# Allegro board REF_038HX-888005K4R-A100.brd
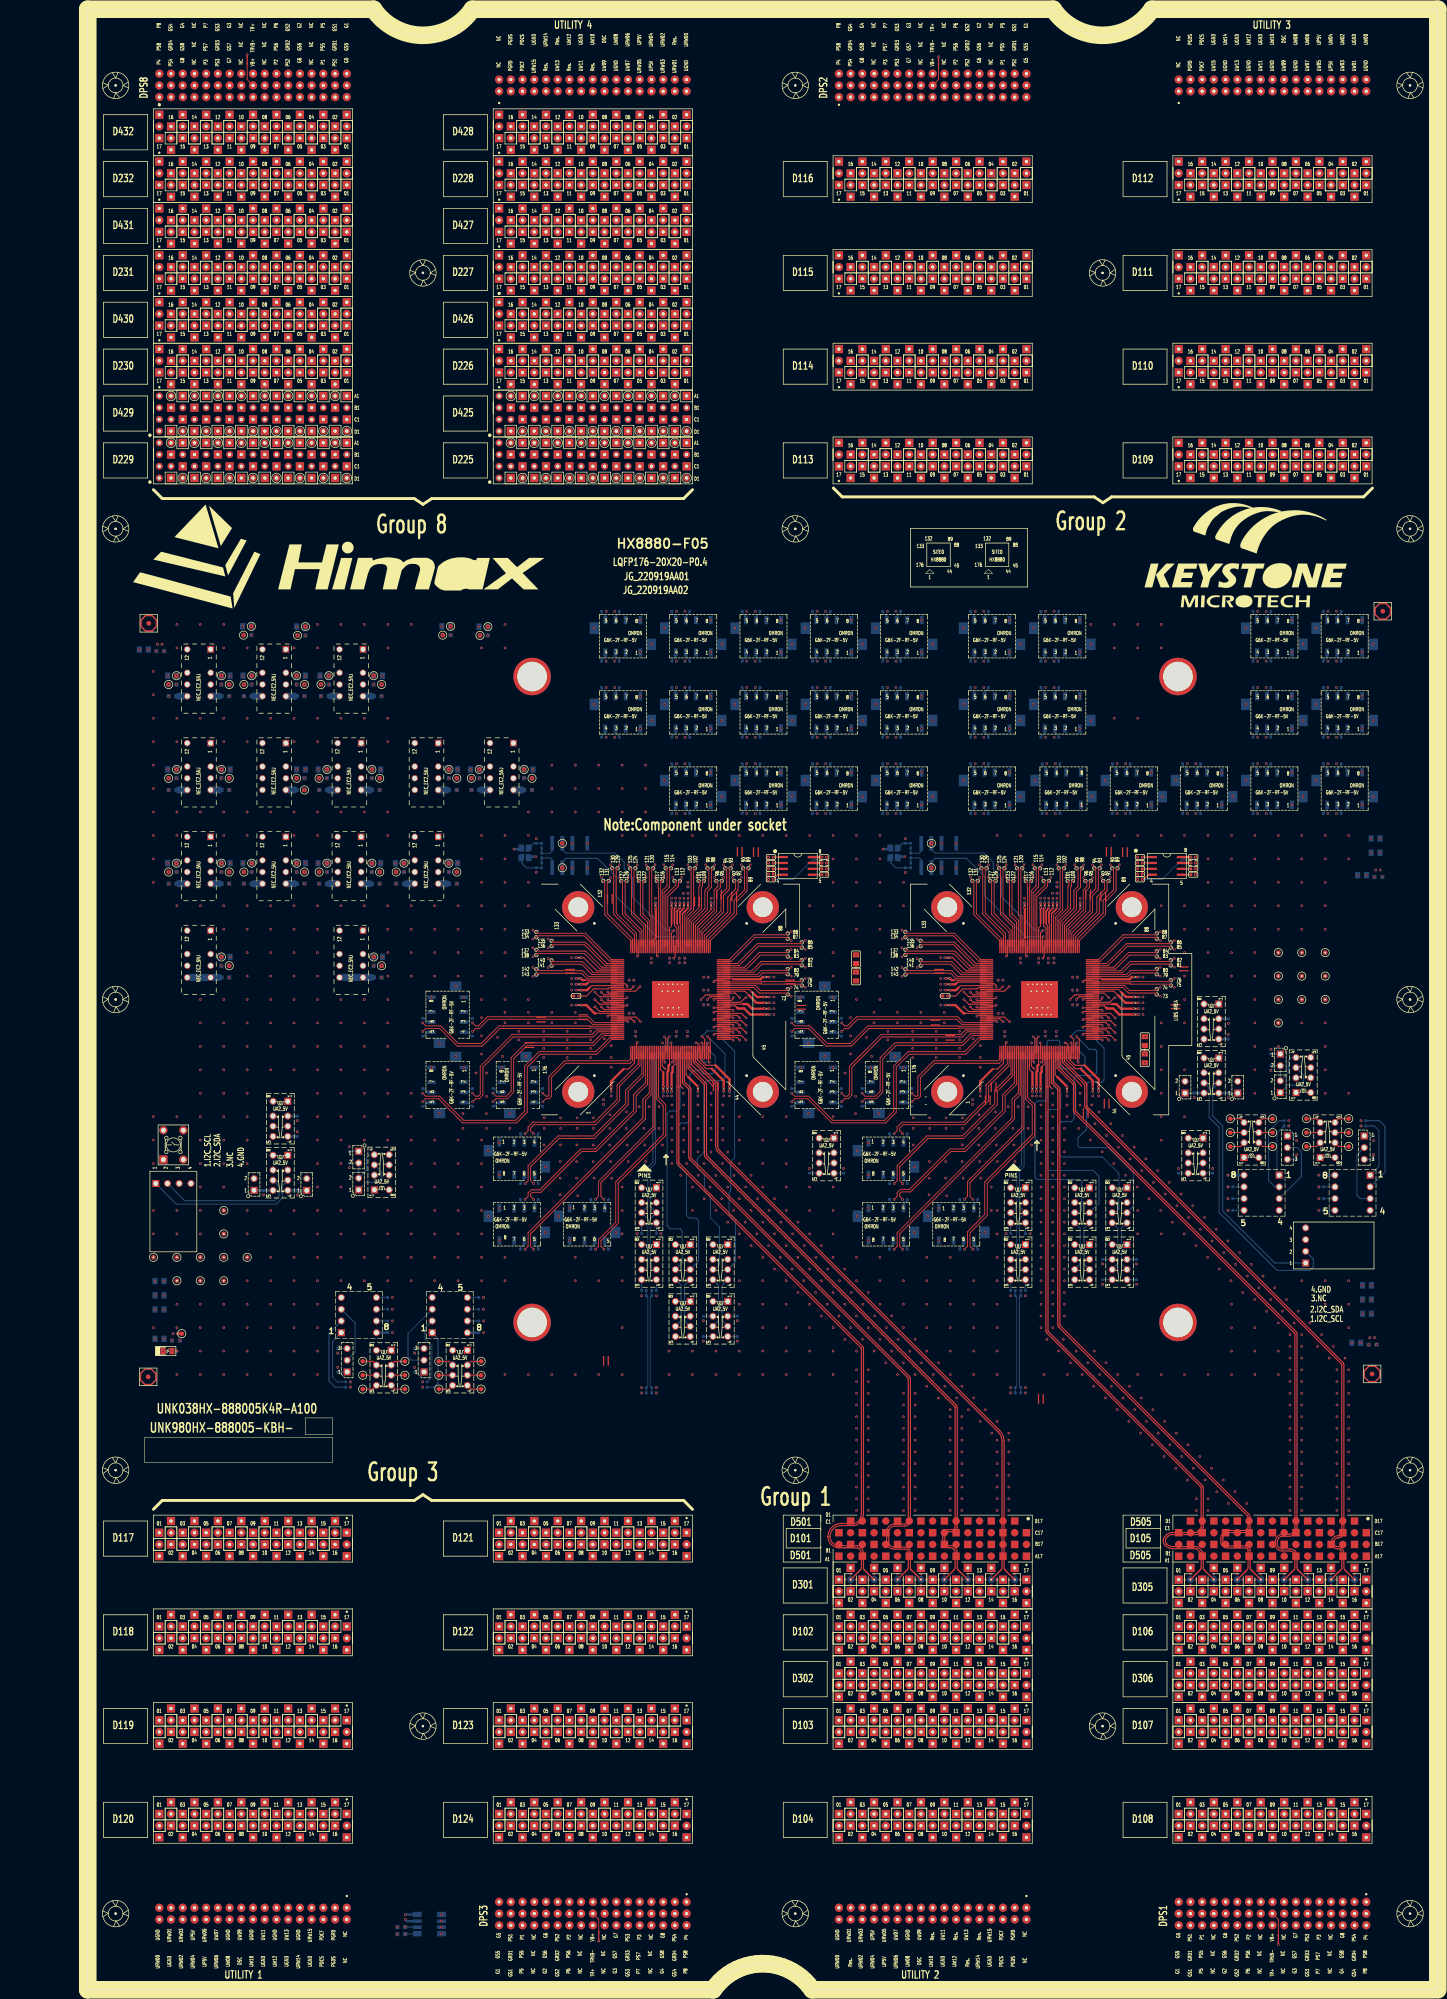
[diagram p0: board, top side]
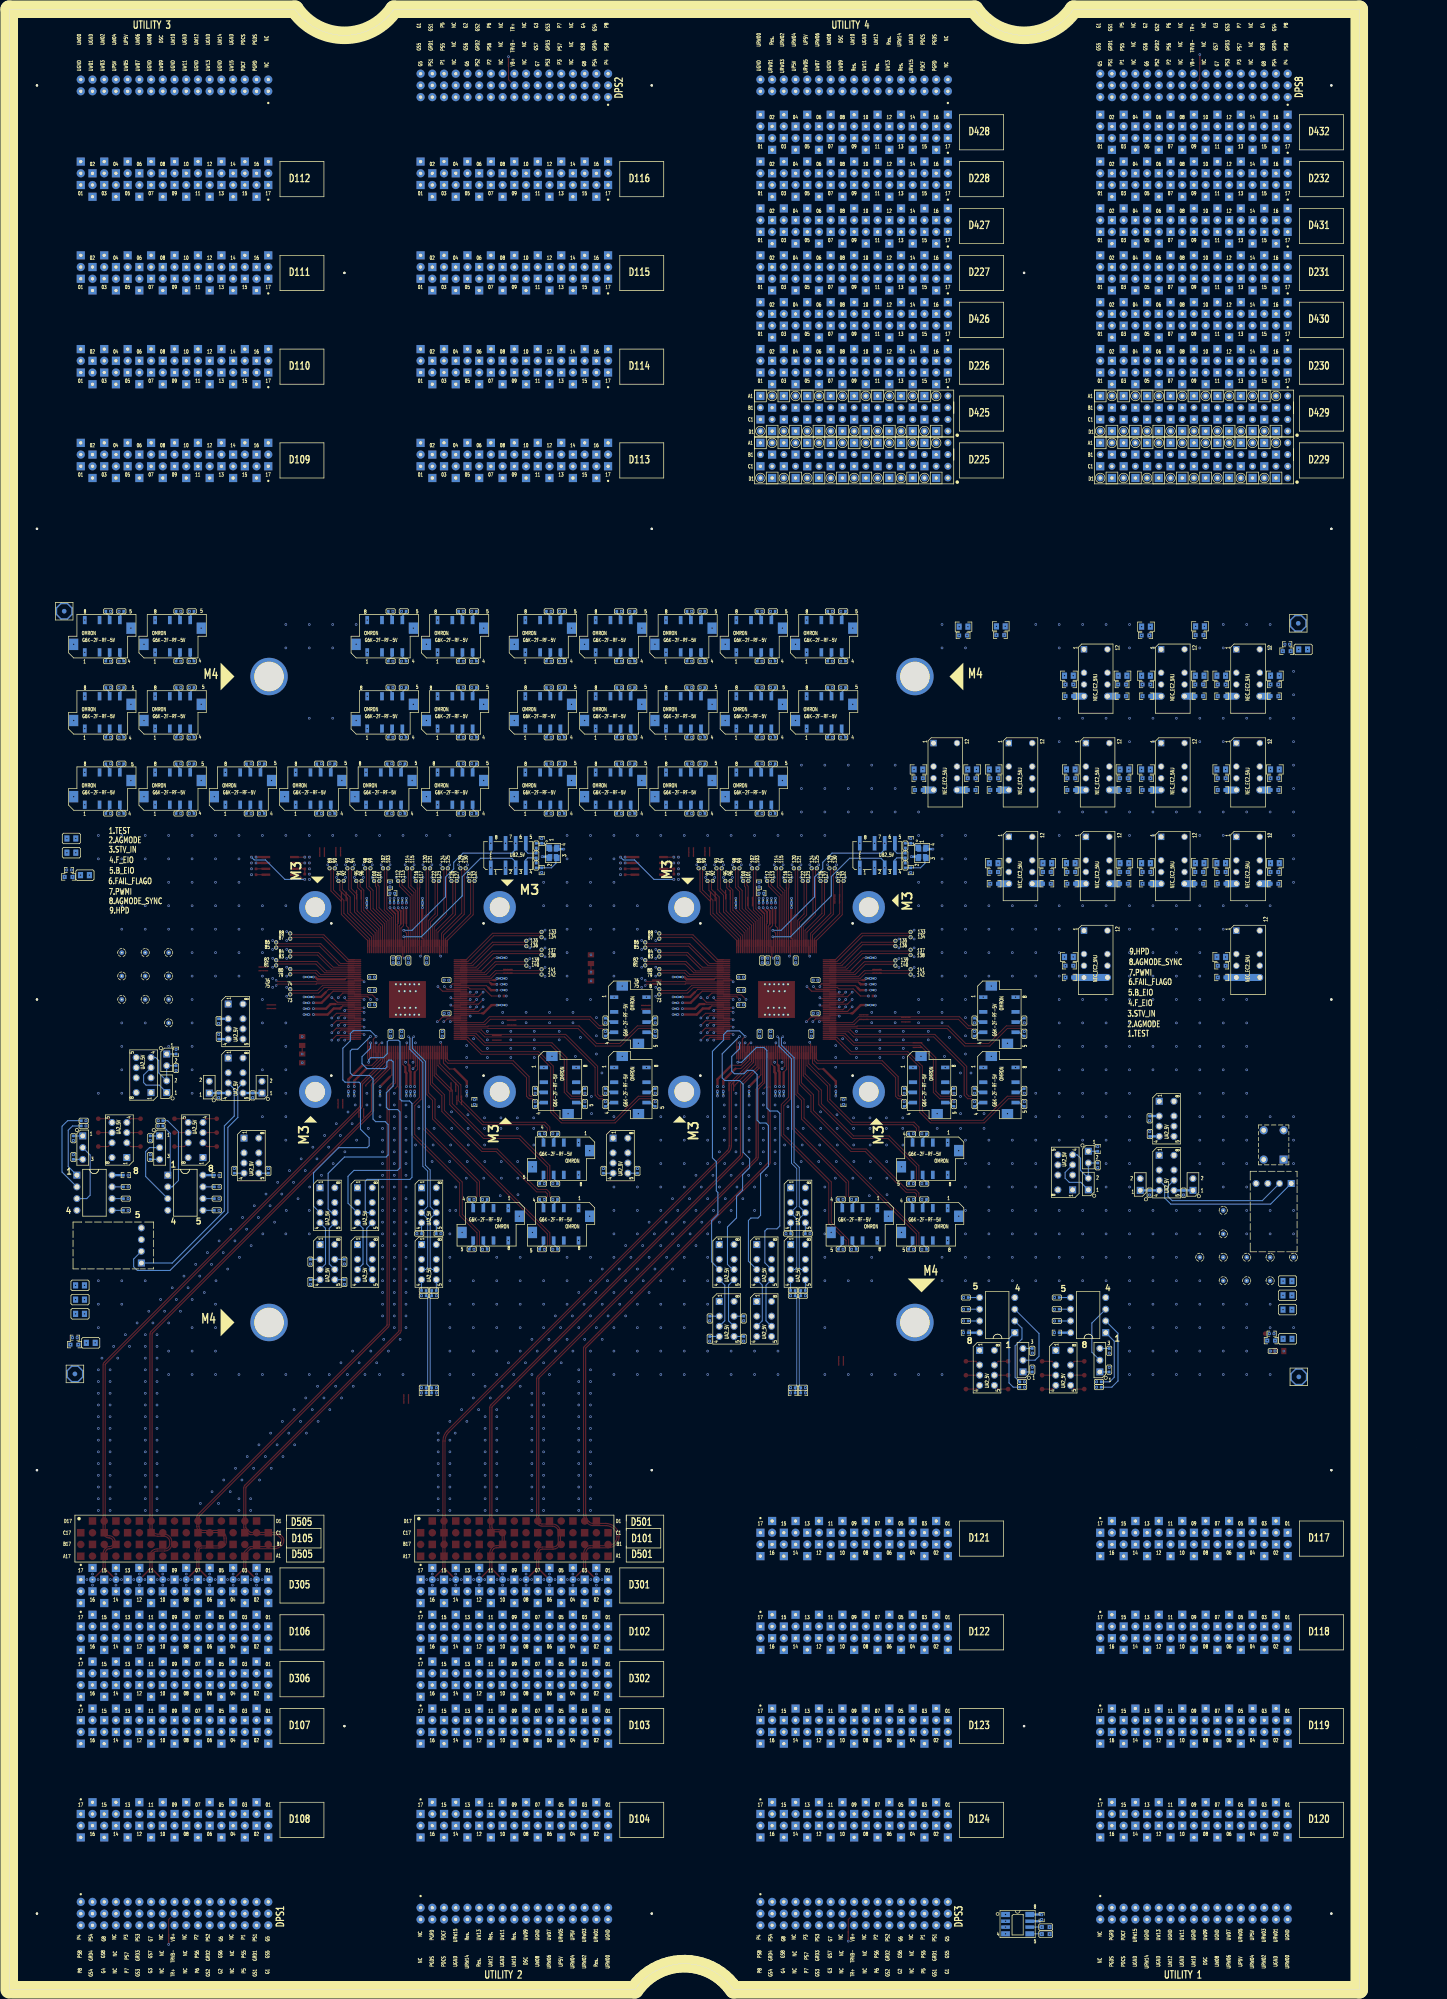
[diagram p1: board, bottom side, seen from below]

Outline 292.64 x 429.26 mm; copper layers: TOP, L02_GND, L03_SIGNAL, L04_GND, L05_SIGNAL, L06_GND, L07_SIGNAL, L08_GND, L09_POWER, L10_GND, L11_POWER, L12_USER, L13_CBIT, L14_POWER, L15_GND, L16_POWER, L17_GND, L18_POWER, L19_GND, L20_SIGNAL, L21_GND, L22_SIGNAL, L23_GND, BOTTOM. Coordinates in mm from the lower left corner of the outline.

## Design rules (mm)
net group 2AUX: nets S1_2AUX+ S1_2AUX-
net group D231_MCB1_E: nets D231_MCB1_E+ D231_MCB1_E-
net group D231_MCB1_EE: nets D231_MCB1_EE+ D231_MCB1_EE-
net group D231_MCB1_F: nets D231_MCB1_F+ D231_MCB1_F-
net group D231_MCB1_FF: nets D231_MCB1_FF+ D231_MCB1_FF-
net group D231_MCB1_G: nets D231_MCB1_G+ D231_MCB1_G-
net group D231_MCB1_GG: nets D231_MCB1_GG+ D231_MCB1_GG-
net group D231_MCB1_H: nets D231_MCB1_H+ D231_MCB1_H-
net group D231_MCB1_HH: nets D231_MCB1_HH+ D231_MCB1_HH-
net group D232_MCB1_E: nets D232_MCB1_E+ D232_MCB1_E-
net group D232_MCB1_EE: nets D232_MCB1_EE+ D232_MCB1_EE-
net group D232_MCB1_F: nets D232_MCB1_F+ D232_MCB1_F-
net group D232_MCB1_FF: nets D232_MCB1_FF+ D232_MCB1_FF-
net group D232_MCB1_G: nets D232_MCB1_G+ D232_MCB1_G-
net group D232_MCB1_GG: nets D232_MCB1_GG+ D232_MCB1_GG-
net group D232_MCB1_H: nets D232_MCB1_H+ D232_MCB1_H-
net group D232_MCB1_HH: nets D232_MCB1_HH+ D232_MCB1_HH-
net group D431_MCB1_A: nets D431_MCB1_A+ D431_MCB1_A-
net group D431_MCB1_AA: nets D431_MCB1_AA+ D431_MCB1_AA-
net group D431_MCB1_B: nets D431_MCB1_B+ D431_MCB1_B-
net group D431_MCB1_BB: nets D431_MCB1_BB+ D431_MCB1_BB-
net group D431_MCB1_C: nets D431_MCB1_C+ D431_MCB1_C-
net group D431_MCB1_CC: nets D431_MCB1_CC+ D431_MCB1_CC-
net group D431_MCB1_D: nets D431_MCB1_D+ D431_MCB1_D-
net group D431_MCB1_DD: nets D431_MCB1_DD+ D431_MCB1_DD-
net group D432_MCB1_A: nets D432_MCB1_A+ D432_MCB1_A-
net group D432_MCB1_AA: nets D432_MCB1_AA+ D432_MCB1_AA-
net group D432_MCB1_B: nets D432_MCB1_B+ D432_MCB1_B-
net group D432_MCB1_BB: nets D432_MCB1_BB+ D432_MCB1_BB-
net group D432_MCB1_C: nets D432_MCB1_C+ D432_MCB1_C-
net group D432_MCB1_CC: nets D432_MCB1_CC+ D432_MCB1_CC-
net group D432_MCB1_D: nets D432_MCB1_D+ D432_MCB1_D-
net group D432_MCB1_DD: nets D432_MCB1_DD+ D432_MCB1_DD-
net group S1_1AUX: nets S1_1AUX+ S1_1AUX-
net group S1_AUXCH: nets S1_AUXCH+ S1_AUXCH-
net group S2_1AUX: nets S2_1AUX+ S2_1AUX-
net group S2_2AUX: nets S2_2AUX+ S2_2AUX-
net group S2_AUXCH: nets S2_AUXCH+ S2_AUXCH-
net group AUX1: nets D12013 D12015 D12406 D12408
net group AUX2: nets D11801 D11803 D12201 D12203
net group CH: nets D10305 D10307 D10309 D10315 D10401 D10402 D10403 D10404 D10405 D10406 D10411 D10416 D10705 D10707 D10709 D10715 D10801 D10802 D10803 D10804 D10805 D10806 D10811 D10816 D11902 D11906 D11911 D12005 D12006 D12007 D12009 D12011 D12105 D12109 D12305 D12312 D12411 D12413 D12415 D12416
net group ELV_RX: nets D11805 D11806 D11807 D11808 D11809 D11810 D11811 D11812 D11813 D11814 D11815 D11816 D12205 D12206 D12207 D12208 D12209 D12210 D12211 D12212 D12213 D12214 D12215 D12216
net group FLASH: nets S1_SPI_CSN S1_SPI_SCK S1_SPI_SDI S1_SPI_SDO S2_SPI_CSN S2_SPI_SCK S2_SPI_SDI S2_SPI_SDO
net group ISP_TX: nets D10901 D10902 D10903 D10904 D10905 D10906 D10907 D10908 D10909 D10910 D10911 D10912 D10913 D10914 D10915 D10916 D11001 D11002 D11003 D11004 D11005 D11006 D11007 D11008 D11009 D11010 D11011 D11012 D11013 D11014 D11015 D11016 D11101 D11102 D11103 D11104 D11105 D11106 D11107 D11108 D11109 D11110 D11111 D11112 D11113 D11114 D11115 D11116 D11209 D11210 D11211 D11212 D11213 D11214 D11215 D11216 D11301 D11302 D11303 D11304 D11305 D11306 D11307 D11308 D11309 D11310 D11311 D11312 D11313 D11314 D11315 D11316 D11401 D11402 D11403 D11404 D11405 D11406 D11407 D11408 D11409 D11410 D11411 D11412 D11413 D11414 D11415 D11416 D11501 D11502 D11503 D11504 D11505 D11506 D11507 D11508 D11509 D11510 D11511 D11512 D11513 D11514 D11515 D11516 D11609 D11610 D11611 D11612 D11613 D11614 D11615 D11616
net group OLV_RX: nets D11702 D11704 D11706 D11708 D11710 D11712 D11713 D11714 D11715 D11716 D11802 D11804 D12102 D12104 D12106 D12108 D12110 D12112 D12113 D12114 D12115 D12116 D12202 D12204
net group RX_9G: nets D30102 D30104 D30106 D30108 D30110 D30112 D30114 D30116 D30502 D30504 D30506 D30508 D30510 D30512 D30514 D30516

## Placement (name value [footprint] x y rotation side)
2SH1  SHORT  [DEFAULT_SHORT_SMALL]  186.95 206.84 180 top
2SH2  SHORT  [DEFAULT_SHORT_SMALL]  186.95 205.83 180 top
2SH3  SHORT  [DEFAULT_SHORT_SMALL]  183.74 210.13 180 top
2SH4  SHORT  [DEFAULT_SHORT_SMALL]  183.74 209.11 180 top
2SH5  SHORT  [DEFAULT_SHORT_SMALL]  235.81 212.66 0 top
2SH6  SHORT  [DEFAULT_SHORT_SMALL]  235.81 213.47 0 top
2SH7  SHORT  [DEFAULT_SHORT_SMALL]  195.85 195.65 270 top
2SH8  SHORT  [DEFAULT_SHORT_SMALL]  196.87 195.65 270 top
2SH9  SHORT  [DEFAULT_SHORT_SMALL]  216.83 190.04 270 top
2SH10  SHORT  [DEFAULT_SHORT_SMALL]  215.81 190.04 270 top
2SH11  SHORT  [DEFAULT_SHORT_SMALL]  237.58 221.67 0 top
2SH12  SHORT  [DEFAULT_SHORT_SMALL]  237.58 220.87 0 top
2SH13  SHORT  [DEFAULT_SHORT_SMALL]  220.82 246.65 90 top
2SH14  SHORT  [DEFAULT_SHORT_SMALL]  221.84 246.65 90 top
2SH15  SHORT  [DEFAULT_SHORT_SMALL]  224.32 246.58 90 top
2SH16  SHORT  [DEFAULT_SHORT_SMALL]  225.33 246.58 90 top
2SH17  SHORT  [DEFAULT_SHORT_SMALL]  219.61 236.96 90 top
2SH18  SHORT  [DEFAULT_SHORT_SMALL]  220.63 236.96 90 top
2SH19  SHORT  [DEFAULT_SHORT_SMALL]  207.11 128.06 270 top
2SH20  SHORT  [DEFAULT_SHORT_SMALL]  206.09 128.06 270 top
2SH21  SHORT  [DEFAULT_SHORT_SMALL]  221.37 192.05 270 top
2SH22  SHORT  [DEFAULT_SHORT_SMALL]  220.35 192.05 270 top
2SH23  SHORT  [DEFAULT_SHORT_SMALL]  217.34 237.35 90 top
2SH24  SHORT  [DEFAULT_SHORT_SMALL]  216.33 237.35 90 top
2SH25  SHORT  [DEFAULT_SHORT_SMALL]  184.54 221.14 180 top
2SH26  SHORT  [DEFAULT_SHORT_SMALL]  184.54 220.34 180 top
2SH27  SHORT  [DEFAULT_SHORT_SMALL]  194.59 192.8 270 top
2SH28  SHORT  [DEFAULT_SHORT_SMALL]  195.61 192.8 270 top
BD29  BD120-3A-S8  [FB0805]  277.29 152.67 0 bottom
BD30  BD120-3A-S8  [FB0805]  15.56 147.42 0 bottom
BD31  BD120-3A-S8  [FB0805]  15.56 150.51 0 bottom
BD32  BD120-3A-S8  [FB0805]  15.56 153.59 0 bottom
BD33  BD120-3A-S8  [FB0805]  15.54 141.08 0 bottom
BD34  BD120-3A-S8  [FB0805]  274.97 140.21 0 bottom
BD35  BD120-3A-S8  [FB0805]  276.22 241.58 0 bottom
BD36  BD120-3A-S8  [FB0805]  279.17 246.45 0 bottom
BD37  BD120-3A-S8  [FB0805]  12.16 290.5 0 bottom
BD38  BD120-3A-S8  [FB0805]  279.17 249.53 0 bottom
BD39  BD120-3A-S8  [FB0805]  277.29 146.5 0 bottom
BD40  BD120-3A-S8  [FB0805]  277.29 149.59 0 bottom
BR902  330-1-S4  [R0402]  18.75 138.43 180 bottom
C3  0.1U-16-X-S4-MU  [C0402]  122.76 129.36 0 bottom
C4  0.1U-16-X-S4-MU  [C0402]  120.56 129.36 180 bottom
C5  22P-50-N-S4-AVX  [C0402]  97.22 248.99 90 bottom
C6  22P-50-N-S4-AVX  [C0402]  97.22 242.67 270 bottom
C7  0.1U-16-X-S4-MU  [C0402]  56.69 182.24 90 bottom
C8  0.1U-16-X-S4-MU  [C0402]  85.27 142.42 0 bottom
C9  0.1U-16-X-S4-MU  [C0402]  65.56 142.42 0 bottom
CA1  NC/10U-10-X6S-S6-MU  [C0603]  95.45 262.58 0 bottom
CA2  NC/47U-10-X5R-S8-TDK  [C0805]  95.55 264.49 0 bottom
CA3  NC/10U-10-X6S-S6-MU  [C0603]  84.02 262.58 180 bottom
CA4  NC/47U-10-X5R-S8-TDK  [C0805]  83.92 264.49 180 bottom
CA5  NC/10U-10-X6S-S6-MU  [C0603]  62.84 221.94 0 bottom
CA6  NC/47U-10-X5R-S8-TDK  [C0805]  62.94 223.85 0 bottom
CA7  NC/10U-10-X6S-S6-MU  [C0603]  62.84 282.9 0 bottom
CA8  NC/47U-10-X5R-S8-TDK  [C0805]  62.94 284.81 0 bottom
CA9  NC/10U-10-X6S-S6-MU  [C0603]  51.41 282.9 180 bottom
CA10  NC/47U-10-X5R-S8-TDK  [C0805]  51.31 284.81 180 bottom
CA11  NC/10U-10-X6S-S6-MU  [C0603]  62.43 262.58 0 bottom
CA12  NC/47U-10-X5R-S8-TDK  [C0805]  62.53 264.49 0 bottom
CA13  NC/47U-10-X5R-S8-TDK  [C0805]  79.25 244.17 0 bottom
CA14  NC/10U-10-X6S-S6-MU  [C0603]  79.15 242.26 0 bottom
CA15  NC/47U-10-X5R-S8-TDK  [C0805]  67.62 244.17 180 bottom
CA16  NC/10U-10-X6S-S6-MU  [C0603]  67.72 242.26 180 bottom
CA17  NC/47U-10-X5R-S8-TDK  [C0805]  62.53 244.17 0 bottom
CA18  NC/10U-10-X6S-S6-MU  [C0603]  62.43 242.26 0 bottom
CA19  NC/47U-10-X5R-S8-TDK  [C0805]  85.78 295.44 180 bottom
CA20  NC/10U-10-X6S-S6-MU  [C0603]  85.88 293.53 180 bottom
CA21  10U-10-X6S-S6-MU  [C0603]  95.45 260.04 0 bottom
CA22  10U-10-X6S-S6-MU  [C0603]  84.02 260.04 180 bottom
CA23  10U-10-X6S-S6-MU  [C0603]  62.84 219.4 0 bottom
CA24  10U-10-X6S-S6-MU  [C0603]  62.84 280.36 0 bottom
CA25  10U-10-X6S-S6-MU  [C0603]  51.41 280.36 180 bottom
CA26  10U-10-X6S-S6-MU  [C0603]  62.43 260.04 0 bottom
CA27  10U-10-X6S-S6-MU  [C0603]  79.15 239.72 0 bottom
CA28  10U-10-X6S-S6-MU  [C0603]  67.72 239.72 180 bottom
CA29  10U-10-X6S-S6-MU  [C0603]  62.43 239.72 0 bottom
CA30  NC/47U-10-X5R-S8-TDK  [C0805]  77.7 295.51 180 bottom
CA31  10U-10-X6S-S6-MU  [C0603]  77.8 293.6 180 bottom
CA32  NC/10U-10-X6S-S6-MU  [C0603]  79.15 262.58 0 bottom
CA33  NC/47U-10-X5R-S8-TDK  [C0805]  79.25 264.49 0 bottom
CA34  10U-10-X6S-S6-MU  [C0603]  79.15 260.04 0 bottom
CA35  NC/10U-10-X6S-S6-MU  [C0603]  51 262.58 180 bottom
CA36  NC/47U-10-X5R-S8-TDK  [C0805]  50.9 264.49 180 bottom
CA37  10U-10-X6S-S6-MU  [C0603]  51 260.04 180 bottom
CA38  NC/10U-10-X6S-S6-MU  [C0603]  51 242.26 180 bottom
CA39  NC/47U-10-X5R-S8-TDK  [C0805]  50.9 244.17 180 bottom
CA40  10U-10-X6S-S6-MU  [C0603]  51 239.72 180 bottom
CB1  0.1U-16-X-S4-MU  [C0402]  18.99 142.21 180 bottom
CB2  10U-25-X-S6  [C0603]  279.78 241.2 180 bottom
CB3  0.1U-16-X-S4-MU  [C0402]  15.61 291.63 180 bottom
CB4  10U-25-X-S6  [C0603]  15.72 290.12 180 bottom
CB5  0.1U-16-X-S4-MU  [C0402]  278.42 141.34 180 bottom
CB6  10U-25-X-S6  [C0603]  278.52 139.83 180 bottom
CB7  0.1U-16-X-S4-MU  [C0402]  279.67 242.7 180 bottom
CB8  10U-25-X-S6  [C0603]  19.1 140.7 180 bottom
CB19  0.1U-16-X-S4-MU  [C0402]  68.85 15.75 90 bottom
CC1  0.47U-10-X6S-S2-TY  [C0201]  113.47 194.12 90 bottom
CC2  4.7U-10-X6T-S4-MU  [C0402]  111.81 192.4 270 bottom
CC4  0.47U-10-X6S-S2-TY  [C0201]  124.77 194.12 90 bottom
CC6  0.47U-10-X6S-S2-TY  [C0201]  125.66 194.12 90 bottom
CC7  0.47U-10-X6S-S2-TY  [C0201]  148.34 212.64 180 bottom
CC8  0.47U-10-X6S-S2-TY  [C0201]  139.12 194.12 90 bottom
CC9  0.47U-10-X6S-S2-TY  [C0201]  105.3 216.66 0 bottom
CC11  0.47U-10-X6S-S2-TY  [C0201]  126.55 194.12 90 bottom
CC13  0.47U-10-X6S-S2-TY  [C0201]  132.26 194.12 90 bottom
CC15  4.7U-2.5-X6S-S2-MU  [C0201]  135.14 234.95 90 bottom
CC16  NC/4.7U-2.5-X6S-S2-MU  [C0201]  148.34 219.5 180 bottom
CC17  4.7U-2.5-X6S-S2-MU  [C0201]  123.06 236.16 270 bottom
CC19  0.47U-10-X6S-S2-TY  [C0201]  128.32 236.16 270 bottom
CC20  4.7U-10-X6T-S4-MU  [C0402]  129.6 237.66 0 bottom
CC22  0.47U-10-X6S-S2-TY  [C0201]  126.54 236.16 270 bottom
CC23  4.7U-10-X6T-S4-MU  [C0402]  130.1 239.53 270 bottom
CC25  0.47U-10-X6S-S2-TY  [C0201]  147.13 215.18 0 bottom
CC26  0.47U-10-X6S-S2-TY  [C0201]  129.21 236.16 270 bottom
CC27  0.47U-10-X6S-S2-TY  [C0201]  135.14 236.16 270 bottom
CC28  0.47U-10-X6S-S2-TY  [C0201]  147.13 219.5 0 top
CC29  0.47U-10-X6S-S2-TY  [C0201]  123.06 234.95 90 bottom
CC30  0.47U-10-X6S-S2-TY  [C0201]  127.43 236.16 270 bottom
CC31  0.47U-10-X6S-S2-TY  [C0201]  148.34 213.91 180 bottom
CC32  0.47U-10-X6S-S2-TY  [C0201]  137.85 194.12 90 bottom
CC33  0.47U-10-X6S-S2-TY  [C0201]  105.3 217.93 0 bottom
CC34  0.47U-10-X6S-S2-TY  [C0201]  105.3 213.41 0 bottom
CC35  0.47U-10-X6S-S2-TY  [C0201]  148.34 211.37 180 bottom
CC36  0.47U-10-X6S-S2-TY  [C0201]  130.1 236.16 270 bottom
CC37  0.47U-10-X6S-S2-TY  [C0201]  105.3 223.69 0 bottom
CC38  NC/4.7U-2.5-X6S-S2-MU  [C0201]  106.52 223.69 180 bottom
CC39  0.47U-10-X6S-S2-TY  [C0201]  105.3 219.2 0 bottom
CC40  4.7U-2.5-X6S-S2-MU  [C0201]  148.34 215.18 180 bottom
CC41  4.7U-2.5-X6S-S2-MU  [C0201]  106.52 219.2 180 bottom
CC42  4.7U-2.5-X6S-S2-MU  [C0201]  106.52 213.41 180 bottom
CD1  0.1U-10-X7R-S2-MU  [C0201]  113.47 195.34 270 top
CD3  0.1U-10-X7R-S2-MU  [C0201]  127.43 234.95 90 top
CD4  0.1U-10-X7R-S2-MU  [C0201]  106.52 216.66 180 top
CD5  0.1U-10-X7R-S2-MU  [C0201]  125.66 195.34 270 top
CD6  0.1U-10-X7R-S2-MU  [C0201]  130.1 234.95 90 top
CD7  0.1U-10-X7R-S2-MU  [C0201]  147.13 212.64 0 top
CD8  0.1U-10-X7R-S2-MU  [C0201]  126.55 195.34 270 top
CD9  0.1U-10-X7R-S2-MU  [C0201]  132.26 195.34 270 top
CD10  0.1U-10-X7R-S2-MU  [C0201]  147.13 219.5 0 bottom
CD11  0.1U-10-X7R-S2-MU  [C0201]  135.14 234.95 90 top
CD12  0.1U-10-X7R-S2-MU  [C0201]  123.06 234.95 90 top
CD13  0.1U-10-X7R-S2-MU  [C0201]  128.32 234.95 90 top
CD14  0.1U-10-X7R-S2-MU  [C0201]  126.54 234.95 90 top
CD15  0.1U-10-X7R-S2-MU  [C0201]  147.13 215.18 0 top
CD16  0.1U-10-X7R-S2-MU  [C0201]  129.21 234.95 90 top
CD17  0.1U-10-X7R-S2-MU  [C0201]  106.52 217.93 180 top
CD18  0.1U-10-X7R-S2-MU  [C0201]  147.13 213.91 0 top
CD19  0.1U-10-X7R-S2-MU  [C0201]  106.52 213.41 180 top
CD20  0.1U-10-X7R-S2-MU  [C0201]  147.13 211.37 0 top
CD21  0.1U-10-X7R-S2-MU  [C0201]  137.85 195.34 270 top
CD22  0.1U-10-X7R-S2-MU  [C0201]  124.77 195.34 270 top
CD23  0.1U-10-X7R-S2-MU  [C0201]  139.12 195.34 270 top
CD24  0.1U-10-X7R-S2-MU  [C0201]  106.52 223.69 180 top
CD25  0.1U-10-X7R-S2-MU  [C0201]  106.52 219.2 180 top
CSDPS225  V93K_CSDPS_DPS32  [PG_VG93K_PF_DPS32_G8D225]  109.49 331.47 0 top
CSDPS229  V93K_CSDPS_DPS32  [PG_VG93K_PF_DPS32_G8D229]  35.83 331.47 0 top
CSDPS425  V93K_CSDPS_DPS32  [PG_VG93K_PF_DPS32_G8D425]  109.49 341.63 0 top
CSDPS429  V93K_CSDPS_DPS32  [PG_VG93K_PF_DPS32_G8D429]  35.83 341.63 0 top
CT1  0.1U-16-X-S4-MU  [C0402]  159.63 244.22 0 top
D101/D501  V93K_PS1600 HD  [PG_VG93K_F_HSM_G1D101_501_ND]  183.15 97.79 0 top
D102  V93K_CH  [PG_VG93K_F_G1D102]  183.15 77.47 0 top
D103  V93K_CH  [PG_VG93K_F_G1D103]  183.15 57.15 0 top
D104  V93K_CH  [PG_VG93K_F_G1D104]  183.15 36.83 0 top
D105/D505  V93K_PS1600 HD  [PG_VG93K_F_HSM_G1D105_505_ND]  256.81 97.79 0 top
D106  V93K_CH  [PG_VG93K_F_G1D106]  256.81 77.47 0 top
D107  V93K_CH  [PG_VG93K_F_G1D107]  256.81 57.15 0 top
D108  V93K_CH  [PG_VG93K_F_G1D108]  256.81 36.83 0 top
D109  V93K_CH  [PG_VG93K_F_G2D109]  256.81 331.47 0 top
D110  V93K_CH  [PG_VG93K_F_G2D110]  256.81 351.79 0 top
D111  V93K_CH  [PG_VG93K_F_G2D111]  256.81 372.11 0 top
D112  V93K_CH  [PG_VG93K_F_G2D112]  256.81 392.43 0 top
D113  V93K_CH  [PG_VG93K_F_G2D113]  183.15 331.47 0 top
D114  V93K_CH  [PG_VG93K_F_G2D114]  183.15 351.79 0 top
D115  V93K_CH  [PG_VG93K_F_G2D115]  183.15 372.11 0 top
D116  V93K_CH  [PG_VG93K_F_G2D116]  183.15 392.43 0 top
D117  V93K_CH  [PG_VG93K_F_G3D117]  35.83 97.79 0 top
D118  V93K_CH  [PG_VG93K_F_G3D118]  35.83 77.47 0 top
D119  V93K_CH  [PG_VG93K_F_G3D119]  35.83 57.15 0 top
D120  V93K_CH  [PG_VG93K_F_G3D120]  35.83 36.83 0 top
D121  V93K_CH  [PG_VG93K_F_G3D121]  109.49 97.79 0 top
D122  V93K_CH  [PG_VG93K_F_G3D122]  109.49 77.47 0 top
D123  V93K_CH  [PG_VG93K_F_G3D123]  109.49 57.15 0 top
D124  V93K_CH  [PG_VG93K_F_G3D124]  109.49 36.83 0 top
D226  V93K_CH  [PG_VG93K_F_G8D226]  109.49 351.79 0 top
D227  V93K_CH  [PG_VG93K_F_G8D227]  109.49 372.11 0 top
D228  V93K_CH  [PG_VG93K_F_G8D228]  109.49 392.43 0 top
D230  V93K_CH  [PG_VG93K_F_G8D230]  35.83 351.79 0 top
D231  V93K_CH  [PG_VG93K_F_G8D231]  35.83 372.11 0 top
D232  V93K_CH  [PG_VG93K_F_G8D232]  35.83 392.43 0 top
D301  V93K_CH  [PG_VG93K_F_G1D301]  183.15 87.63 0 top
D302  V93K_CH  [PG_VG93K_F_G1D302]  183.15 67.31 0 top
D305  V93K_CH  [PG_VG93K_F_G1D305]  256.81 87.63 0 top
D306  V93K_CH  [PG_VG93K_F_G1D306]  256.81 67.31 0 top
D426  V93K_CH  [PG_VG93K_F_G8D426]  109.49 361.95 0 top
D427  V93K_CH  [PG_VG93K_F_G8D427]  109.49 382.27 0 top
D428  V93K_CH  [PG_VG93K_F_G8D428]  109.49 402.59 0 top
D430  V93K_CH  [PG_VG93K_F_G8D430]  35.83 361.95 0 top
D431  V93K_CH  [PG_VG93K_F_G8D431]  35.83 382.27 0 top
D432  V93K_CH  [PG_VG93K_F_G8D432]  35.83 402.59 0 top
DPS1  V93K_DPS  [PG_VG93K_F_G1DPS1]  256.81 16.51 0 top
DPS2  V93K_DPS  [PG_VG93K_F_G2DPS2]  183.15 412.75 0 top
DPS3  V93K_DPS  [PG_VG93K_F_G3DPS3]  109.49 16.51 0 top
DPS8  V93K_DPS  [PG_VG93K_F_G8DPS8]  35.83 412.75 0 top
FD1  -  [FD_040_V2]  13.1 132.84 0 top
FD2  -  [FD_040_V2]  278.4 133.48 0 top
FD3  -  [FD_040_V2]  280.72 298.78 0 top
FD4  -  [FD_040_V2]  13.22 296.16 0 top
FD5  -  [FD_040_V2]  13.22 296.16 180 bottom
FD6  -  [FD_040_V2]  280.72 298.78 180 bottom
FD7  -  [FD_040_V2]  278.4 133.48 180 bottom
FD8  -  [FD_040_V2]  13.1 132.84 180 bottom
GND1  TP01  [TP_040_T]  80 262.58 0 top
GND2  TP01  [TP_040_T]  33.85 282.9 180 top
GND3  TP01  [TP_040_T]  63.28 242.26 0 top
GND4  TP01  [TP_040_T]  50.56 282.9 180 top
GND5  TP01  [TP_040_T]  63.69 282.9 0 top
GND6  TP01  [TP_040_T]  50.15 262.58 180 top
GND7  TP01  [TP_040_T]  63.28 262.58 0 top
GND8  TP01  [TP_040_T]  50.15 242.26 180 top
GND9  TP01  [TP_040_T]  46.98 282.9 0 top
GND10  TP01  [TP_040_T]  30.67 221.94 0 top
GND11  TP01  [TP_040_T]  80 242.26 0 top
GND12  TP01  [TP_040_T]  33.77 293.6 180 top
GND13  TP01  [TP_040_T]  45.48 293.53 180 top
GND14  TP01  [TP_040_T]  66.87 242.26 180 top
HX8880-F05  REF-CODE-CHIP  [CHIP_CODE]  -12.35 119.28 0 top
J1  HDR-2X1-M  [JP_2P_100]  58.73 181.74 0 bottom
J2  HDR-3X1-M  [JP_3P_100]  72.89 133.91 180 bottom
J3  HDR-3X1-M  [JP_3P_100]  56.23 133.91 180 bottom
J4  HDR-2X1-M  [JP_2P_100]  47.47 173.27 180 bottom
J5  HDR-2X1-M  [JP_2P_100]  36.04 173.27 180 bottom
JG_220919AA01  REF-CODE-SOCKET  [SOCKET_CODE]  -17 212.43 0 top
JG_220919AA02  REF-CODE-SOCKET  [SOCKET_CODE]  -17 214.21 0 top
K1  G6K-2F-RF-5V-A  [RL_OMRONG6K2FRF_5V]  176.96 276.85 180 bottom
K2  G6K-2F-RF-5V-A  [RL_OMRONG6K2FRF_5V]  176.96 260.34 180 bottom
K3  G6K-2F-RF-5V-A  [RL_OMRONG6K2FRF_5V]  176.96 293.36 180 bottom
K4  G6K-2F-RF-5V-A  [RL_OMRONG6K2FRF_5V]  161.72 293.36 180 bottom
K5  G6K-2F-RF-5V-A  [RL_OMRONG6K2FRF_5V]  161.72 260.34 180 bottom
K6  G6K-2F-RF-5V-A  [RL_OMRONG6K2FRF_5V]  161.72 276.85 180 bottom
K7  G6K-2F-RF-5V-A  [RL_OMRONG6K2FRF_5V]  146.48 293.36 180 bottom
K8  G6K-2F-RF-5V-A  [RL_OMRONG6K2FRF_5V]  146.48 260.34 180 bottom
K9  UA2-5NJ-A-V3  [RL_NECUA2_5V_V3]  121.66 157.91 90 bottom
K10  UA2-5NJ-A-V3  [RL_NECUA2_5V_V3]  63.73 176.98 270 bottom
K11  G6K-2F-RF-5V-A  [RL_OMRONG6K2FRF_5V]  146.48 276.85 180 bottom
K12  UA2-5NJ-A-V3  [RL_NECUA2_5V_V3]  121.66 170.23 90 bottom
K13  UA2-5NJ-A-V3  [RL_NECUA2_5V_V3]  160.15 180.99 90 bottom
K14  UA2-5NJ-A-V3  [RL_NECUA2_5V_V3]  137.12 157.91 90 bottom
K15  UA2-5NJ-A-V3  [RL_NECUA2_5V_V3]  128.99 157.91 90 bottom
K16  G6K-2F-RF-5V-A  [RL_OMRONG6K2FRF_5V]  131.24 260.34 180 bottom
K17  G6K-2F-RF-5V-A  [RL_OMRONG6K2FRF_5V]  131.24 276.85 180 bottom
K18  UB2-5NU-B  [RL_NECUB2_5V]  104.46 245.83 0 bottom
K19  UA2-5NJ-A-V3  [RL_NECUA2_5V_V3]  128.99 145.59 90 bottom
K20  UA2-5NJ-A-V3  [RL_NECUA2_5V_V3]  137.12 145.59 90 bottom
K21  G6K-2F-RF-5V-A  [RL_OMRONG6K2FRF_5V]  131.24 293.36 180 bottom
K22  G6K-2F-RF-5V-A  [RL_OMRONG6K2FRF_5V]  93.03 180.12 0 bottom
K23  G6K-2F-RF-5V-A  [RL_OMRONG6K2FRF_5V]  108.27 165.9 0 bottom
K24  G6K-2F-RF-5V-A  [RL_OMRONG6K2FRF_5V]  93.03 165.9 0 bottom
K25  G6K-2F-RF-5V-A  [RL_OMRONG6K2FRF_5V]  78 211.34 270 bottom
K26  G6K-2F-RF-5V-A  [RL_OMRONG6K2FRF_5V]  93.24 196.1 270 bottom
K27  G6K-2F-RF-5V-A  [RL_OMRONG6K2FRF_5V]  78 196.1 270 bottom
K28  UA2-5NJ-A-V3  [RL_NECUA2_5V_V3]  41.76 177.27 90 bottom
K29  G6K-2F-RF-5V-A  [RL_OMRONG6K2FRF_5V]  116 276.85 180 bottom
K30  G6K-2F-RF-5V-A  [RL_OMRONG6K2FRF_5V]  116 293.36 180 bottom
K31  EC2-5NJ-A  [RL_NECEC2_10P_5V]  73.43 263.85 90 bottom
K33  NC/UA2-5NJ-A-V3  [RL_NECUA2_5V_V3]  41.76 188.97 90 bottom
K34  EC2-5NJ-A  [RL_NECEC2_10P_5V]  89.74 263.85 90 bottom
K36  EC2-5NJ-A  [RL_NECEC2_10P_5V]  57.12 223.21 90 bottom
K37  EC2-5NJ-A  [RL_NECEC2_10P_5V]  57.12 284.17 90 bottom
K39  EC2-5NJ-A  [RL_NECEC2_10P_5V]  56.72 263.85 90 bottom
K40  EC2-5NJ-A  [RL_NECEC2_10P_5V]  73.43 243.53 90 bottom
K42  EC2-5NJ-A  [RL_NECEC2_10P_5V]  56.72 243.53 90 bottom
LD902  LDG-2-S8  [LED_0805]  17.3 138.43 0 top
LOGO1  -  [LOGO_KT_KSMT]  247.92 303.94 0 top
LOGO2  LOGO_HX_Himax  [LOGO_HX_HIMAX]  52.96 305.37 0 top
LQFP176-20X20-P0.4  REF-CODE-CHIP  [CHIP_CODE]  -12.35 117.51 0 top
NOREF  -  []  114.82 213.23 90 top
NOREF#2  -  []  110.74 189.63 90 top
NOREF#3  -  []  116.32 204.63 90 top
NOREF#4  -  []  137.82 206.03 90 top
NOREF#5  -  []  134.92 203.13 90 top
NOREF#6  -  []  113.33 201.63 90 top
NOREF#7  -  []  113.94 202.25 0 top
NOREF#8  -  []  116.32 224.63 0 top
NOREF#9  -  []  113.33 227.63 0 top
NOREF#10  -  []  151.32 221.84 0 top
NOREF#11  -  []  0 0 90 top
NOREF#12  -  []  93.32 224.01 0 top
NOREF#13  -  []  98.32 237.25 0 top
NOREF#14  -  []  109.82 198.13 90 top
NOREF#15  -  []  151.32 233.47 0 top
NOREF#16  -  []  0 429.26 0 top
NOREF#17  -  []  96.32 284.63 0 top
NOREF#18  -  []  138.69 202.25 90 top
NOREF#19  -  []  119.84 197.13 90 top
NOREF#20  -  []  108.82 213.75 0 top
NOREF#21  -  []  106.32 234.63 0 top
NOREF#22  -  []  101.32 225.69 0 top
NOREF#23  -  []  96.32 144.63 90 top
NOREF#24  -  []  122.52 226.13 0 top
NOREF#25  -  []  109.82 231.13 0 top
R1  NC/1M-1-S4  [R0402]  122.76 130.5 180 bottom
R2  NC/1M-1-S4  [R0402]  120.56 150.42 0 bottom
R3  NC/100K-1-S4  [R0402]  122.76 150.42 0 bottom
R4  NC/100K-1-S4  [R0402]  120.56 130.5 0 bottom
R5  0-5-S4  [R0402]  98.39 243.67 270 bottom
R6  1M-1-S4  [R0402]  98.39 245.83 270 bottom
R7  49.9-1-S4  [R0402]  175.69 271.45 0 bottom
R8  49.9-1-S4  [R0402]  172.83 271.45 0 bottom
R9  49.9-1-S4  [R0402]  175.69 282.26 0 bottom
R10  49.9-1-S4  [R0402]  172.83 282.26 0 bottom
R11  49.9-1-S4  [R0402]  175.69 254.94 0 bottom
R12  49.9-1-S4  [R0402]  172.83 254.94 0 bottom
R13  49.9-1-S4  [R0402]  175.69 265.75 0 bottom
R14  49.9-1-S4  [R0402]  172.83 265.75 0 bottom
R15  49.9-1-S4  [R0402]  175.69 287.96 0 bottom
R16  49.9-1-S4  [R0402]  172.83 287.96 0 bottom
R17  49.9-1-S4  [R0402]  175.69 298.77 0 bottom
R18  49.9-1-S4  [R0402]  172.83 298.77 0 bottom
R19  49.9-1-S4  [R0402]  160.45 287.96 0 bottom
R20  49.9-1-S4  [R0402]  157.59 287.96 0 bottom
R21  49.9-1-S4  [R0402]  160.45 298.77 0 bottom
R22  49.9-1-S4  [R0402]  157.59 298.77 0 bottom
R23  49.9-1-S4  [R0402]  160.45 254.94 0 bottom
R24  49.9-1-S4  [R0402]  157.59 254.94 0 bottom
R25  49.9-1-S4  [R0402]  160.45 265.75 0 bottom
R26  49.9-1-S4  [R0402]  157.59 265.75 0 bottom
R27  49.9-1-S4  [R0402]  160.45 271.45 0 bottom
R28  49.9-1-S4  [R0402]  157.59 271.45 0 bottom
R29  49.9-1-S4  [R0402]  160.45 282.26 0 bottom
R30  49.9-1-S4  [R0402]  157.59 282.26 0 bottom
R31  49.9-1-S4  [R0402]  145.21 287.96 0 bottom
R32  49.9-1-S4  [R0402]  142.35 287.96 0 bottom
R33  49.9-1-S4  [R0402]  145.21 298.77 0 bottom
R34  49.9-1-S4  [R0402]  142.35 298.77 0 bottom
R35  49.9-1-S4  [R0402]  145.21 254.94 0 bottom
R36  49.9-1-S4  [R0402]  142.35 254.94 0 bottom
R37  49.9-1-S4  [R0402]  145.21 265.75 0 bottom
R38  49.9-1-S4  [R0402]  142.35 265.75 0 bottom
R39  49.9-1-S4  [R0402]  145.21 271.45 0 bottom
R40  49.9-1-S4  [R0402]  142.35 271.45 0 bottom
R41  49.9-1-S4  [R0402]  145.21 282.26 0 bottom
R42  49.9-1-S4  [R0402]  142.35 282.26 0 bottom
R43  49.9-1-S4  [R0402]  114.73 282.26 0 bottom
R44  49.9-1-S4  [R0402]  111.87 282.26 0 bottom
R45  49.9-1-S4  [R0402]  94.3 174.72 180 bottom
R46  49.9-1-S4  [R0402]  97.16 174.72 180 bottom
R47  49.9-1-S4  [R0402]  109.54 171.3 180 bottom
R48  49.9-1-S4  [R0402]  112.4 171.3 180 bottom
R49  49.9-1-S4  [R0402]  109.54 160.49 180 bottom
R50  49.9-1-S4  [R0402]  112.4 160.49 180 bottom
R51  49.9-1-S4  [R0402]  94.3 171.3 180 bottom
R52  49.9-1-S4  [R0402]  97.16 171.3 180 bottom
R53  49.9-1-S4  [R0402]  94.3 160.49 180 bottom
R54  49.9-1-S4  [R0402]  97.16 160.49 180 bottom
R55  49.9-1-S4  [R0402]  83.41 210.07 90 bottom
R56  49.9-1-S4  [R0402]  83.41 207.21 90 bottom
R57  49.9-1-S4  [R0402]  72.6 210.07 90 bottom
R58  49.9-1-S4  [R0402]  72.6 207.21 90 bottom
R59  49.9-1-S4  [R0402]  98.65 194.83 90 bottom
R60  49.9-1-S4  [R0402]  98.65 191.97 90 bottom
R61  49.9-1-S4  [R0402]  87.84 194.83 90 bottom
R62  49.9-1-S4  [R0402]  87.84 191.97 90 bottom
R63  49.9-1-S4  [R0402]  114.73 287.96 0 bottom
R64  49.9-1-S4  [R0402]  111.87 287.96 0 bottom
R65  49.9-1-S4  [R0402]  72.6 194.83 90 bottom
R66  49.9-1-S4  [R0402]  72.6 191.97 90 bottom
R67  49.9-1-S4  [R0402]  129.97 254.94 0 bottom
R68  49.9-1-S4  [R0402]  127.11 254.94 0 bottom
R69  49.9-1-S4  [R0402]  129.97 265.75 0 bottom
R70  49.9-1-S4  [R0402]  127.11 265.75 0 bottom
R71  49.9-1-S4  [R0402]  129.97 271.45 0 bottom
R72  49.9-1-S4  [R0402]  127.11 271.45 0 bottom
R73  49.9-1-S4  [R0402]  129.97 282.26 0 bottom
R74  49.9-1-S4  [R0402]  127.11 282.26 0 bottom
R75  49.9-1-S4  [R0402]  129.97 287.96 0 bottom
R76  49.9-1-S4  [R0402]  127.11 287.96 0 bottom
R77  49.9-1-S4  [R0402]  129.97 298.77 0 bottom
R78  49.9-1-S4  [R0402]  127.11 298.77 0 bottom
R79  49.9-1-S4  [R0402]  114.73 271.45 0 bottom
R80  49.9-1-S4  [R0402]  111.87 271.45 0 bottom
R82  4.7K-1-S4-WA  [R0402]  45.45 188.87 270 bottom
R83  4.7K-1-S4-WA  [R0402]  45.44 172.77 90 bottom
R84  4.7K-1-S4-WA  [R0402]  38.08 172.77 90 bottom
R85  100K-1-S4  [R0402]  56.69 178.7 90 bottom
R86  4.7K-1-S4-WA  [R0402]  70.86 138.49 270 bottom
R87  4.7K-1-S4-WA  [R0402]  73.09 130.61 180 bottom
R88  4.7K-1-S4-WA  [R0402]  73.09 131.75 180 bottom
R89  4.7K-1-S4-WA  [R0402]  70.86 134.41 90 bottom
R90  4.7K-1-S4-WA  [R0402]  85.27 144.96 0 bottom
R91  4.7K-1-S4-WA  [R0402]  85.27 147.5 0 bottom
R92  4.7K-1-S4-WA  [R0402]  85.27 150.04 0 bottom
R93  4.7K-1-S4-WA  [R0402]  54.2 138.49 270 bottom
R94  4.7K-1-S4-WA  [R0402]  56.42 131.75 0 bottom
R95  4.7K-1-S4-WA  [R0402]  56.42 130.61 0 bottom
R96  4.7K-1-S4-WA  [R0402]  54.2 134.41 90 bottom
R97  4.7K-1-S4-WA  [R0402]  65.56 144.96 0 bottom
R98  4.7K-1-S4-WA  [R0402]  65.56 147.5 0 bottom
R99  4.7K-1-S4-WA  [R0402]  65.56 150.04 0 bottom
R100  49.9-1-S4  [R0402]  114.73 298.77 0 bottom
R101  49.9-1-S4  [R0402]  111.87 298.77 0 bottom
R102  49.9-1-S4  [R0402]  94.3 185.53 180 bottom
R103  49.9-1-S4  [R0402]  97.16 185.53 180 bottom
R104  49.9-1-S4  [R0402]  83.41 194.83 90 bottom
R105  49.9-1-S4  [R0402]  83.41 191.97 90 bottom
R117  1K-1-S4  [R0402]  45.41 185.47 90 bottom
R118  NC/0-5-S4  [R0402]  105.9 215.39 180 top
R119  4.7K-1-S4-WA  [R0402]  163.84 177.49 270 bottom
R120  4.7K-1-S4-WA  [R0402]  156.45 177.49 270 bottom
R125  0-5-S4  [R0402]  140.81 145.49 270 bottom
R126  0-5-S4  [R0402]  140.81 141.09 270 bottom
R127  0-5-S4  [R0402]  133.44 145.49 270 bottom
R128  0-5-S4  [R0402]  133.44 141.09 270 bottom
R129  0-5-S4  [R0402]  122.76 151.56 180 bottom
R130  0-5-S4  [R0402]  120.56 151.56 0 bottom
R131  50-0.1-S4-HF-VI  [R0402]  123.76 163.88 0 bottom
R132  50-0.1-S4-HF-VI  [R0402]  119.56 163.88 180 bottom
R133  0-5-S4  [R0402]  98.39 247.99 90 bottom
RB1  10K-1-S6  [R0603]  67.96 13.59 0 bottom
RB2  10K-1-S6  [R0603]  67.96 12.06 0 bottom
RP1  0-5-S4  [R0402]  118.77 207.19 90 bottom
RP2  0-5-S4  [R0402]  117.86 211.63 0 bottom
RP3  0-5-S4  [R0402]  133.98 213.47 180 bottom
RP4  0-5-S4  [R0402]  127.57 207.19 90 bottom
RP5  0-5-S4  [R0402]  129.97 207.19 90 bottom
RP6  0-5-S4  [R0402]  133.98 219.47 180 bottom
RP7  0-5-S4  [R0402]  128.23 223.09 270 bottom
RP8  0-5-S4  [R0402]  126.12 223.09 270 bottom
RP9  0-5-S4  [R0402]  133.98 216.67 180 bottom
RP10  0-5-S4  [R0402]  129.43 223.09 270 bottom
RP11  0-5-S4  [R0402]  122.16 223.09 270 bottom
RP12  0-5-S4  [R0402]  117.86 218.83 0 bottom
RT1  10K-1-S4  [R0402]  148.07 244.22 0 top
RT2  10K-1-S4  [R0402]  148.07 245.49 0 top
RT3  10K-1-S4  [R0402]  148.07 241.81 180 top
RT4  10K-1-S4  [R0402]  148.07 240.67 180 top
RT5  NC/10K-1-S4  [R0402]  148.07 242.95 180 top
RT6  NC/10K-1-S4  [R0402]  159.63 245.49 180 top
RT7  NC/10K-1-S4  [R0402]  159.63 242.95 180 top
RT8  NC/10K-1-S4  [R0402]  159.63 241.68 180 top
RT9  RTD-100-S8  [R0805]  166.54 223.37 90 top
RT10  0-5-S8  [R0805]  166.52 219.61 90 top
S1_I2C  HDR-4X1-MR-A  [JP_4P_100_R90_V1]  14.75 174.75 270 top
S1_RST_N  HDR-2X1-M  [JP_2P_100]  58.73 173.38 180 bottom
SB1  SHORT  [DEFAULT_SHORT_SMALL]  258.08 11.04 90 top
SB2  SHORT  [DEFAULT_SHORT_SMALL]  184.42 417.83 270 top
SB3  SHORT  [DEFAULT_SHORT_SMALL]  110.76 11.71 90 top
SB8  SHORT  [DEFAULT_SHORT_SMALL]  34.56 418.32 270 top
SCREW1  V93KHSCREW  [PG_VG93K_F_HALFOUTLINE]  146.32 214.63 0 top
SH1  SHORT  [DEFAULT_SHORT_SMALL]  95.75 205.26 180 top
SH2  SHORT  [DEFAULT_SHORT_SMALL]  95.75 204.25 180 top
SH3  SHORT  [DEFAULT_SHORT_SMALL]  98.29 210.79 180 top
SH4  SHORT  [DEFAULT_SHORT_SMALL]  98.29 209.77 180 top
SH5  SHORT  [DEFAULT_SHORT_SMALL]  154.64 212.54 0 top
SH6  SHORT  [DEFAULT_SHORT_SMALL]  154.64 213.34 0 top
SH7  SHORT  [DEFAULT_SHORT_SMALL]  113.68 236.42 90 top
SH8  SHORT  [DEFAULT_SHORT_SMALL]  112.66 236.42 90 top
SH9  SHORT  [DEFAULT_SHORT_SMALL]  131.53 235.85 90 top
SH10  SHORT  [DEFAULT_SHORT_SMALL]  132.55 235.85 90 top
SH11  SHORT  [DEFAULT_SHORT_SMALL]  152.27 218.83 0 top
SH12  SHORT  [DEFAULT_SHORT_SMALL]  152.27 218.03 0 top
SH13  SHORT  [DEFAULT_SHORT_SMALL]  140.82 246.65 90 top
SH14  SHORT  [DEFAULT_SHORT_SMALL]  141.84 246.65 90 top
SH15  SHORT  [DEFAULT_SHORT_SMALL]  144.32 246.58 90 top
SH16  SHORT  [DEFAULT_SHORT_SMALL]  145.33 246.58 90 top
SH17  SHORT  [DEFAULT_SHORT_SMALL]  139.61 236.96 90 top
SH18  SHORT  [DEFAULT_SHORT_SMALL]  140.63 236.96 90 top
SH19  SHORT  [DEFAULT_SHORT_SMALL]  111.82 136.31 90 top
SH20  SHORT  [DEFAULT_SHORT_SMALL]  112.84 136.31 90 top
SH21  SHORT  [DEFAULT_SHORT_SMALL]  136.63 195.82 270 top
SH22  SHORT  [DEFAULT_SHORT_SMALL]  135.62 195.82 270 top
SH23  SHORT  [DEFAULT_SHORT_SMALL]  137.34 237.35 90 top
SH24  SHORT  [DEFAULT_SHORT_SMALL]  136.33 237.35 90 top
SH25  SHORT  [DEFAULT_SHORT_SMALL]  104.54 221.14 180 top
SH26  SHORT  [DEFAULT_SHORT_SMALL]  104.54 220.34 180 top
SH27  SHORT  [DEFAULT_SHORT_SMALL]  107.41 211.31 180 top
SH28  SHORT  [DEFAULT_SHORT_SMALL]  107.41 210.29 180 top
SITE1  CU/HX8880-F05-LQFP176-20X20  [SK_LQFP176P_0P4MM_JG_HX8880]  126.32 214.63 90 top
SITE2  CU/HX8880-F05-LQFP176-20X20  [SK_LQFP176P_0P4MM_JG_HX8880]  206.32 214.63 90 top
SK1  UA2-5NJ-A-V3  [RL_NECUA2_5V_V3]  80.69 135 90 bottom
SK1_2  TP01  [TP_040_T]  85.27 136.21 270 top
SK1_3  TP01  [TP_040_T]  85.27 133.2 270 top
SK1_4  TP01  [TP_040_T]  85.27 130.19 270 top
SK1_5  TP01  [TP_040_T]  76.11 130.19 90 top
SK1_6  TP01  [TP_040_T]  76.11 133.2 90 top
SK1_7  TP01  [TP_040_T]  76.11 136.21 90 top
SK2  UA2-5NJ-A-V3  [RL_NECUA2_5V_V3]  64.18 135 90 bottom
SK2_2  TP01  [TP_040_T]  68.76 136.21 270 top
SK2_3  TP01  [TP_040_T]  68.76 133.2 270 top
SK2_4  TP01  [TP_040_T]  68.76 130.19 270 top
SK2_5  TP01  [TP_040_T]  59.6 130.19 90 top
SK2_6  TP01  [TP_040_T]  59.6 133.2 90 top
SK2_7  TP01  [TP_040_T]  59.6 136.21 90 top
SKB1  V93K_SKB_140X140MM  [SOCKET_BASE_152X152_V0090A]  166.32 214.63 0 top
SW1  SW-TACTILE-1-D4.5  [SW_4P_UTP0030B-EVB]  18.56 183.12 90 top
TP_AUXVCC  TP01  [TP_040_T]  86.73 295.44 180 top
TP_AVDD11_RX  TP01  [TP_040_T]  52.26 284.81 180 top
TP_AVDD11_XTAL  TP01  [TP_040_T]  78.3 264.49 0 top
TP_AVDD18_RX  TP01  [TP_040_T]  61.99 284.81 0 top
TP_PLL_M_VDD33  TP01  [TP_040_T]  78.3 244.17 0 top
TP_PLL_TX_VDD33  TP01  [TP_040_T]  68.57 244.17 180 top
TP_VCC3V3  TP01  [TP_040_T]  78.65 295.51 180 top
TP_VDD_IO_33  TP01  [TP_040_T]  84.87 264.49 180 top
TP_VDD_TXREG_33_B  TP01  [TP_040_T]  61.58 244.17 0 top
TP_VDD_TXREG_33_T  TP01  [TP_040_T]  51.85 244.17 180 top
TP_VDDA_33_LV  TP01  [TP_040_T]  94.6 264.49 0 top
TP_VDDC_11  TP01  [TP_040_T]  61.99 223.85 0 top
TP_VDDTXPST_11_B  TP01  [TP_040_T]  61.58 264.49 0 top
TP_VDDTXPST_11_T  TP01  [TP_040_T]  51.85 264.49 180 top
TP_XTAL_IN  TP01  [TP_040_T]  102.86 243.18 0 top
TP_XTAL_OUT  TP01  [TP_040_T]  102.86 248.48 0 top
TPL1  TPL01  [TPL_040_014_TB]  268.24 224.79 0 top
TPL2  TPL01  [TPL_040_014_TB]  268.24 219.71 0 top
TPL3  TPL01  [TPL_040_014_TB]  268.24 214.63 0 top
TPL4  TPL01  [TPL_040_014_TB]  263.16 224.79 0 top
TPL5  TPL01  [TPL_040_014_TB]  263.16 219.71 0 top
TPL6  TPL01  [TPL_040_014_TB]  263.16 214.63 0 top
TPL7  TPL01  [TPL_040_014_TB]  258.08 224.79 0 top
TPL8  TPL01  [TPL_040_014_TB]  258.08 219.71 0 top
TPL9  TPL01  [TPL_040_014_TB]  258.08 214.63 0 top
TPL10  TPL01  [TPL_040_014_TB]  258.08 209.55 0 top
TPL11  TPL01  [TPL_040_014_TB]  29.48 153.67 0 top
TPL12  TPL01  [TPL_040_014_TB]  29.48 158.75 0 top
TPL13  TPL01  [TPL_040_014_TB]  24.4 158.75 0 top
TPL14  TPL01  [TPL_040_014_TB]  24.4 153.67 0 top
TPL15  TPL01  [TPL_040_014_TB]  29.48 168.91 0 top
TPL16  TPL01  [TPL_040_014_TB]  29.48 163.83 0 top
TPL17  TPL01  [TPL_040_014_TB]  19.32 158.75 0 top
TPL18  TPL01  [TPL_040_014_TB]  34.56 158.75 0 top
TPL19  TPL01  [TPL_040_014_TB]  19.32 153.67 0 top
TPL20  TPL01  [TPL_040_014_TB]  14.24 158.75 0 top
U1  SOLDER-DIP8-SOCKET  [DIP8_300X100_RLPIN]  74.67 142.42 0 bottom
U2  SOLDER-DIP8-SOCKET  [DIP8_300X100_RLPIN]  54.96 142.42 0 bottom
UB1  AT24C04N-SO8  [SO8_206X050]  74.06 14.22 180 bottom
UNK1SK1_2  TP01  [TP_040_T]  247.67 182.77 0 top
UNK1SK1_3  TP01  [TP_040_T]  247.67 185.78 0 top
UNK1SK1_4  TP01  [TP_040_T]  247.67 188.79 0 top
UNK1SK1_5  TP01  [TP_040_T]  256.82 188.79 0 top
UNK1SK1_6  TP01  [TP_040_T]  256.82 185.78 0 top
UNK1SK1_7  TP01  [TP_040_T]  256.82 182.77 0 top
UNK1SK2_2  TP01  [TP_040_T]  264.18 182.77 0 top
UNK1SK2_3  TP01  [TP_040_T]  264.18 185.78 0 top
UNK1SK2_4  TP01  [TP_040_T]  264.18 188.79 0 top
UNK1SK2_5  TP01  [TP_040_T]  273.33 188.79 0 top
UNK1SK2_6  TP01  [TP_040_T]  273.33 185.78 0 top
UNK1SK2_7  TP01  [TP_040_T]  273.33 182.77 0 top
UNK2C3  0.1U-16-X-S4-MU  [C0402]  202.76 129.36 0 bottom
UNK2C4  0.1U-16-X-S4-MU  [C0402]  200.56 129.36 180 bottom
UNK2C5  22P-50-N-S4-AVX  [C0402]  177.22 248.99 90 bottom
UNK2C6  22P-50-N-S4-AVX  [C0402]  177.22 242.67 270 bottom
UNK2C7  0.1U-16-X-S4-MU  [C0402]  256.47 203.32 90 bottom
UNK2C8  0.1U-16-X-S4-MU  [C0402]  247.67 176.56 180 bottom
UNK2C9  0.1U-16-X-S4-MU  [C0402]  267.38 176.56 180 bottom
UNK2CA1  NC/10U-10-X6S-S6-MU  [C0603]  46.13 282.9 0 bottom
UNK2CA2  NC/47U-10-X5R-S8-TDK  [C0805]  46.23 284.81 0 bottom
UNK2CA3  NC/10U-10-X6S-S6-MU  [C0603]  34.7 282.9 180 bottom
UNK2CA4  NC/47U-10-X5R-S8-TDK  [C0805]  34.6 284.81 180 bottom
UNK2CA5  NC/10U-10-X6S-S6-MU  [C0603]  29.82 221.94 0 bottom
UNK2CA6  NC/47U-10-X5R-S8-TDK  [C0805]  29.92 223.85 0 bottom
UNK2CA7  NC/10U-10-X6S-S6-MU  [C0603]  29.82 282.9 0 bottom
UNK2CA8  NC/47U-10-X5R-S8-TDK  [C0805]  29.92 284.81 0 bottom
UNK2CA9  NC/10U-10-X6S-S6-MU  [C0603]  18.39 282.9 180 bottom
UNK2CA10  NC/47U-10-X5R-S8-TDK  [C0805]  18.29 284.81 180 bottom
UNK2CA11  NC/10U-10-X6S-S6-MU  [C0603]  29.82 262.58 0 bottom
UNK2CA12  NC/47U-10-X5R-S8-TDK  [C0805]  29.92 264.49 0 bottom
UNK2CA13  NC/47U-10-X5R-S8-TDK  [C0805]  46.23 244.17 0 bottom
UNK2CA14  NC/10U-10-X6S-S6-MU  [C0603]  46.13 242.26 0 bottom
UNK2CA15  NC/47U-10-X5R-S8-TDK  [C0805]  34.6 244.17 180 bottom
UNK2CA16  NC/10U-10-X6S-S6-MU  [C0603]  34.7 242.26 180 bottom
UNK2CA17  NC/47U-10-X5R-S8-TDK  [C0805]  29.92 244.17 0 bottom
UNK2CA18  NC/10U-10-X6S-S6-MU  [C0603]  29.82 242.26 0 bottom
UNK2CA19  NC/47U-10-X5R-S8-TDK  [C0805]  46.23 295.44 180 bottom
UNK2CA20  NC/10U-10-X6S-S6-MU  [C0603]  46.33 293.53 180 bottom
UNK2CA21  10U-10-X6S-S6-MU  [C0603]  46.13 280.36 0 bottom
UNK2CA22  10U-10-X6S-S6-MU  [C0603]  34.7 280.36 180 bottom
UNK2CA23  10U-10-X6S-S6-MU  [C0603]  29.82 219.4 0 bottom
UNK2CA24  10U-10-X6S-S6-MU  [C0603]  29.82 280.36 0 bottom
UNK2CA25  10U-10-X6S-S6-MU  [C0603]  18.39 280.36 180 bottom
UNK2CA26  10U-10-X6S-S6-MU  [C0603]  29.82 260.04 0 bottom
UNK2CA27  10U-10-X6S-S6-MU  [C0603]  46.13 239.72 0 bottom
UNK2CA28  10U-10-X6S-S6-MU  [C0603]  34.7 239.72 180 bottom
UNK2CA29  10U-10-X6S-S6-MU  [C0603]  29.82 239.72 0 bottom
UNK2CA30  NC/47U-10-X5R-S8-TDK  [C0805]  34.52 295.51 180 bottom
UNK2CA31  10U-10-X6S-S6-MU  [C0603]  34.62 293.6 180 bottom
UNK2CA32  NC/10U-10-X6S-S6-MU  [C0603]  46.13 262.58 0 bottom
UNK2CA33  NC/47U-10-X5R-S8-TDK  [C0805]  46.23 264.49 0 bottom
UNK2CA34  10U-10-X6S-S6-MU  [C0603]  46.13 260.04 0 bottom
UNK2CA35  NC/10U-10-X6S-S6-MU  [C0603]  18.39 262.58 180 bottom
UNK2CA36  NC/47U-10-X5R-S8-TDK  [C0805]  18.29 264.49 180 bottom
UNK2CA37  10U-10-X6S-S6-MU  [C0603]  18.39 260.04 180 bottom
UNK2CA38  NC/10U-10-X6S-S6-MU  [C0603]  18.39 242.26 180 bottom
UNK2CA39  NC/47U-10-X5R-S8-TDK  [C0805]  18.29 244.17 180 bottom
UNK2CA40  10U-10-X6S-S6-MU  [C0603]  18.39 239.72 180 bottom
UNK2CC1  0.47U-10-X6S-S2-TY  [C0201]  193.47 194.12 90 bottom
UNK2CC2  4.7U-10-X6T-S4-MU  [C0402]  191.81 192.4 270 bottom
UNK2CC4  0.47U-10-X6S-S2-TY  [C0201]  204.77 194.12 90 bottom
UNK2CC6  0.47U-10-X6S-S2-TY  [C0201]  205.66 194.12 90 bottom
UNK2CC7  0.47U-10-X6S-S2-TY  [C0201]  228.34 212.64 180 bottom
UNK2CC8  0.47U-10-X6S-S2-TY  [C0201]  219.12 194.12 90 bottom
UNK2CC9  0.47U-10-X6S-S2-TY  [C0201]  185.3 216.66 0 bottom
UNK2CC11  0.47U-10-X6S-S2-TY  [C0201]  206.55 194.12 90 bottom
UNK2CC13  0.47U-10-X6S-S2-TY  [C0201]  212.26 194.12 90 bottom
UNK2CC15  4.7U-2.5-X6S-S2-MU  [C0201]  215.14 234.95 90 bottom
UNK2CC16  NC/4.7U-2.5-X6S-S2-MU  [C0201]  228.34 219.5 180 bottom
UNK2CC17  4.7U-2.5-X6S-S2-MU  [C0201]  203.06 236.16 270 bottom
UNK2CC19  0.47U-10-X6S-S2-TY  [C0201]  208.32 236.16 270 bottom
UNK2CC20  4.7U-10-X6T-S4-MU  [C0402]  209.6 237.66 0 bottom
UNK2CC22  0.47U-10-X6S-S2-TY  [C0201]  206.54 236.16 270 bottom
UNK2CC23  4.7U-10-X6T-S4-MU  [C0402]  210.1 239.53 270 bottom
UNK2CC25  0.47U-10-X6S-S2-TY  [C0201]  227.13 215.18 0 bottom
UNK2CC26  0.47U-10-X6S-S2-TY  [C0201]  209.21 236.16 270 bottom
UNK2CC27  0.47U-10-X6S-S2-TY  [C0201]  215.14 236.16 270 bottom
UNK2CC28  0.47U-10-X6S-S2-TY  [C0201]  227.13 219.5 0 top
UNK2CC29  0.47U-10-X6S-S2-TY  [C0201]  203.06 234.95 90 bottom
UNK2CC30  0.47U-10-X6S-S2-TY  [C0201]  207.43 236.16 270 bottom
UNK2CC31  0.47U-10-X6S-S2-TY  [C0201]  228.34 213.91 180 bottom
UNK2CC32  0.47U-10-X6S-S2-TY  [C0201]  217.85 194.12 90 bottom
UNK2CC33  0.47U-10-X6S-S2-TY  [C0201]  185.3 217.93 0 bottom
UNK2CC34  0.47U-10-X6S-S2-TY  [C0201]  185.3 213.41 0 bottom
UNK2CC35  0.47U-10-X6S-S2-TY  [C0201]  228.34 211.37 180 bottom
UNK2CC36  0.47U-10-X6S-S2-TY  [C0201]  210.1 236.16 270 bottom
UNK2CC37  0.47U-10-X6S-S2-TY  [C0201]  185.3 223.69 0 bottom
UNK2CC38  NC/4.7U-2.5-X6S-S2-MU  [C0201]  186.52 223.69 180 bottom
UNK2CC39  0.47U-10-X6S-S2-TY  [C0201]  185.3 219.2 0 bottom
UNK2CC40  4.7U-2.5-X6S-S2-MU  [C0201]  228.34 215.18 180 bottom
UNK2CC41  4.7U-2.5-X6S-S2-MU  [C0201]  186.52 219.2 180 bottom
UNK2CC42  4.7U-2.5-X6S-S2-MU  [C0201]  186.52 213.41 180 bottom
UNK2CD1  0.1U-10-X7R-S2-MU  [C0201]  193.47 195.34 270 top
UNK2CD3  0.1U-10-X7R-S2-MU  [C0201]  207.43 234.95 90 top
UNK2CD4  0.1U-10-X7R-S2-MU  [C0201]  186.52 216.66 180 top
UNK2CD5  0.1U-10-X7R-S2-MU  [C0201]  205.66 195.34 270 top
UNK2CD6  0.1U-10-X7R-S2-MU  [C0201]  210.1 234.95 90 top
UNK2CD7  0.1U-10-X7R-S2-MU  [C0201]  227.13 212.64 0 top
UNK2CD8  0.1U-10-X7R-S2-MU  [C0201]  206.55 195.34 270 top
UNK2CD9  0.1U-10-X7R-S2-MU  [C0201]  212.26 195.34 270 top
UNK2CD10  0.1U-10-X7R-S2-MU  [C0201]  227.13 219.5 0 bottom
UNK2CD11  0.1U-10-X7R-S2-MU  [C0201]  215.14 234.95 90 top
UNK2CD12  0.1U-10-X7R-S2-MU  [C0201]  203.06 234.95 90 top
UNK2CD13  0.1U-10-X7R-S2-MU  [C0201]  208.32 234.95 90 top
UNK2CD14  0.1U-10-X7R-S2-MU  [C0201]  206.54 234.95 90 top
UNK2CD15  0.1U-10-X7R-S2-MU  [C0201]  227.13 215.18 0 top
UNK2CD16  0.1U-10-X7R-S2-MU  [C0201]  209.21 234.95 90 top
UNK2CD17  0.1U-10-X7R-S2-MU  [C0201]  186.52 217.93 180 top
UNK2CD18  0.1U-10-X7R-S2-MU  [C0201]  227.13 213.91 0 top
UNK2CD19  0.1U-10-X7R-S2-MU  [C0201]  186.52 213.41 180 top
UNK2CD20  0.1U-10-X7R-S2-MU  [C0201]  227.13 211.37 0 top
UNK2CD21  0.1U-10-X7R-S2-MU  [C0201]  217.85 195.34 270 top
UNK2CD22  0.1U-10-X7R-S2-MU  [C0201]  204.77 195.34 270 top
UNK2CD23  0.1U-10-X7R-S2-MU  [C0201]  219.12 195.34 270 top
UNK2CD24  0.1U-10-X7R-S2-MU  [C0201]  186.52 223.69 180 top
UNK2CD25  0.1U-10-X7R-S2-MU  [C0201]  186.52 219.2 180 top
UNK2CT1  0.1U-16-X-S4-MU  [C0402]  239.63 244.22 0 top
UNK2GND1  TP01  [TP_040_T]  46.98 260.04 0 top
UNK2GND2  TP01  [TP_040_T]  83.17 262.58 180 top
UNK2GND3  TP01  [TP_040_T]  30.67 242.26 0 top
UNK2GND4  TP01  [TP_040_T]  17.54 282.9 180 top
UNK2GND5  TP01  [TP_040_T]  30.67 282.9 0 top
UNK2GND6  TP01  [TP_040_T]  17.54 262.58 180 top
UNK2GND7  TP01  [TP_040_T]  30.67 262.58 0 top
UNK2GND8  TP01  [TP_040_T]  17.54 242.26 180 top
UNK2GND9  TP01  [TP_040_T]  96.3 262.58 0 top
UNK2GND10  TP01  [TP_040_T]  63.69 221.94 0 top
UNK2GND11  TP01  [TP_040_T]  46.98 242.26 0 top
UNK2GND12  TP01  [TP_040_T]  76.95 293.6 180 top
UNK2GND13  TP01  [TP_040_T]  85.03 293.53 180 top
UNK2GND14  TP01  [TP_040_T]  33.85 242.26 180 top
UNK2J1  HDR-2X1-M  [JP_2P_100]  258.5 202.82 0 bottom
UNK2J2  HDR-3X1-M  [JP_3P_100]  260.04 185.07 0 bottom
UNK2J3  HDR-3X1-M  [JP_3P_100]  276.7 185.07 0 bottom
UNK2J4  HDR-2X1-M  [JP_2P_100]  249.28 194.35 180 bottom
UNK2J5  HDR-2X1-M  [JP_2P_100]  237.85 194.35 180 bottom
UNK2K1  G6K-2F-RF-5V-A  [RL_OMRONG6K2FRF_5V]  272.46 260.34 180 bottom
UNK2K2  G6K-2F-RF-5V-A  [RL_OMRONG6K2FRF_5V]  272.46 276.85 180 bottom
UNK2K3  G6K-2F-RF-5V-A  [RL_OMRONG6K2FRF_5V]  272.46 293.36 180 bottom
UNK2K4  G6K-2F-RF-5V-A  [RL_OMRONG6K2FRF_5V]  257.22 293.36 180 bottom
UNK2K5  G6K-2F-RF-5V-A  [RL_OMRONG6K2FRF_5V]  257.22 260.34 180 bottom
UNK2K6  G6K-2F-RF-5V-A  [RL_OMRONG6K2FRF_5V]  257.22 276.85 180 bottom
UNK2K7  G6K-2F-RF-5V-A  [RL_OMRONG6K2FRF_5V]  241.98 260.34 180 bottom
UNK2K8  G6K-2F-RF-5V-A  [RL_OMRONG6K2FRF_5V]  226.74 260.34 180 bottom
UNK2K9  UA2-5NJ-A-V3  [RL_NECUA2_5V_V3]  201.66 157.91 90 bottom
UNK2K10  UA2-5NJ-A-V3  [RL_NECUA2_5V_V3]  263.51 198.06 270 bottom
UNK2K11  G6K-2F-RF-5V-A  [RL_OMRONG6K2FRF_5V]  211.24 293.36 180 bottom
UNK2K12  UA2-5NJ-A-V3  [RL_NECUA2_5V_V3]  201.66 170.23 90 bottom
UNK2K13  UA2-5NJ-A-V3  [RL_NECUA2_5V_V3]  240.15 180.99 90 bottom
UNK2K14  UA2-5NJ-A-V3  [RL_NECUA2_5V_V3]  223.67 170.23 90 bottom
UNK2K15  UA2-5NJ-A-V3  [RL_NECUA2_5V_V3]  215.54 170.23 90 bottom
UNK2K16  G6K-2F-RF-5V-A  [RL_OMRONG6K2FRF_5V]  211.24 276.85 180 bottom
UNK2K17  G6K-2F-RF-5V-A  [RL_OMRONG6K2FRF_5V]  211.5 260.34 180 bottom
UNK2K18  UB2-5NU-B  [RL_NECUB2_5V]  184.46 245.83 0 bottom
UNK2K19  UA2-5NJ-A-V3  [RL_NECUA2_5V_V3]  215.54 157.91 90 bottom
UNK2K20  UA2-5NJ-A-V3  [RL_NECUA2_5V_V3]  223.67 157.91 90 bottom
UNK2K21  G6K-2F-RF-5V-A  [RL_OMRONG6K2FRF_5V]  196 293.36 180 bottom
UNK2K22  G6K-2F-RF-5V-A  [RL_OMRONG6K2FRF_5V]  173.03 180.12 0 bottom
UNK2K23  G6K-2F-RF-5V-A  [RL_OMRONG6K2FRF_5V]  188.27 165.9 0 bottom
UNK2K24  G6K-2F-RF-5V-A  [RL_OMRONG6K2FRF_5V]  173.03 165.9 0 bottom
UNK2K25  G6K-2F-RF-5V-A  [RL_OMRONG6K2FRF_5V]  158 211.34 270 bottom
UNK2K26  G6K-2F-RF-5V-A  [RL_OMRONG6K2FRF_5V]  173.24 196.1 270 bottom
UNK2K27  G6K-2F-RF-5V-A  [RL_OMRONG6K2FRF_5V]  158 196.1 270 bottom
UNK2K28  UA2-5NJ-A-V3  [RL_NECUA2_5V_V3]  243.57 198.35 90 bottom
UNK2K29  G6K-2F-RF-5V-A  [RL_OMRONG6K2FRF_5V]  196 276.85 180 bottom
UNK2K30  G6K-2F-RF-5V-A  [RL_OMRONG6K2FRF_5V]  196 260.34 180 bottom
UNK2K31  EC2-5NJ-A  [RL_NECEC2_10P_5V]  40.41 263.85 90 bottom
UNK2K33  NC/UA2-5NJ-A-V3  [RL_NECUA2_5V_V3]  243.57 210.05 90 bottom
UNK2K34  EC2-5NJ-A  [RL_NECEC2_10P_5V]  40.41 284.17 90 bottom
UNK2K36  EC2-5NJ-A  [RL_NECEC2_10P_5V]  24.1 223.21 90 bottom
UNK2K37  EC2-5NJ-A  [RL_NECEC2_10P_5V]  24.1 284.17 90 bottom
UNK2K39  EC2-5NJ-A  [RL_NECEC2_10P_5V]  24.1 263.85 90 bottom
UNK2K40  EC2-5NJ-A  [RL_NECEC2_10P_5V]  40.41 243.53 90 bottom
UNK2K42  EC2-5NJ-A  [RL_NECEC2_10P_5V]  24.1 243.53 90 bottom
UNK2R1  NC/1M-1-S4  [R0402]  202.76 130.5 180 bottom
UNK2R2  NC/1M-1-S4  [R0402]  200.56 150.42 0 bottom
UNK2R3  NC/100K-1-S4  [R0402]  202.76 150.42 0 bottom
UNK2R4  NC/100K-1-S4  [R0402]  200.56 130.5 0 bottom
UNK2R5  0-5-S4  [R0402]  178.38 243.67 270 bottom
UNK2R6  1M-1-S4  [R0402]  178.38 245.83 270 bottom
UNK2R7  49.9-1-S4  [R0402]  271.19 254.94 0 bottom
UNK2R8  49.9-1-S4  [R0402]  268.33 254.94 0 bottom
UNK2R9  49.9-1-S4  [R0402]  271.19 265.75 0 bottom
UNK2R10  49.9-1-S4  [R0402]  268.33 265.75 0 bottom
UNK2R11  49.9-1-S4  [R0402]  271.19 271.45 0 bottom
UNK2R12  49.9-1-S4  [R0402]  268.33 271.45 0 bottom
UNK2R13  49.9-1-S4  [R0402]  271.19 282.26 0 bottom
UNK2R14  49.9-1-S4  [R0402]  268.33 282.26 0 bottom
UNK2R15  49.9-1-S4  [R0402]  271.19 287.96 0 bottom
UNK2R16  49.9-1-S4  [R0402]  268.33 287.96 0 bottom
UNK2R17  49.9-1-S4  [R0402]  271.19 298.77 0 bottom
UNK2R18  49.9-1-S4  [R0402]  268.33 298.77 0 bottom
UNK2R19  49.9-1-S4  [R0402]  255.95 287.96 0 bottom
UNK2R20  49.9-1-S4  [R0402]  253.09 287.96 0 bottom
UNK2R21  49.9-1-S4  [R0402]  255.95 298.77 0 bottom
UNK2R22  49.9-1-S4  [R0402]  253.09 298.77 0 bottom
UNK2R23  49.9-1-S4  [R0402]  255.95 254.94 0 bottom
UNK2R24  49.9-1-S4  [R0402]  253.09 254.94 0 bottom
UNK2R25  49.9-1-S4  [R0402]  255.95 265.75 0 bottom
UNK2R26  49.9-1-S4  [R0402]  253.09 265.75 0 bottom
UNK2R27  49.9-1-S4  [R0402]  255.95 271.45 0 bottom
UNK2R28  49.9-1-S4  [R0402]  253.09 271.45 0 bottom
UNK2R29  49.9-1-S4  [R0402]  255.95 282.26 0 bottom
UNK2R30  49.9-1-S4  [R0402]  253.09 282.26 0 bottom
UNK2R31  49.9-1-S4  [R0402]  240.71 254.94 0 bottom
UNK2R32  49.9-1-S4  [R0402]  237.85 254.94 0 bottom
UNK2R33  49.9-1-S4  [R0402]  240.71 265.75 0 bottom
UNK2R34  49.9-1-S4  [R0402]  237.85 265.75 0 bottom
UNK2R35  49.9-1-S4  [R0402]  225.47 254.94 0 bottom
UNK2R36  49.9-1-S4  [R0402]  222.61 254.94 0 bottom
UNK2R37  49.9-1-S4  [R0402]  225.47 265.75 0 bottom
UNK2R38  49.9-1-S4  [R0402]  222.61 265.75 0 bottom
UNK2R39  49.9-1-S4  [R0402]  209.97 287.96 0 bottom
UNK2R40  49.9-1-S4  [R0402]  207.11 287.96 0 bottom
UNK2R41  49.9-1-S4  [R0402]  209.97 298.77 0 bottom
UNK2R42  49.9-1-S4  [R0402]  207.11 298.77 0 bottom
UNK2R43  49.9-1-S4  [R0402]  194.73 282.26 0 bottom
UNK2R44  49.9-1-S4  [R0402]  191.87 282.26 0 bottom
UNK2R45  49.9-1-S4  [R0402]  174.3 174.72 180 bottom
UNK2R46  49.9-1-S4  [R0402]  177.16 174.72 180 bottom
UNK2R47  49.9-1-S4  [R0402]  189.54 171.3 180 bottom
UNK2R48  49.9-1-S4  [R0402]  192.4 171.3 180 bottom
UNK2R49  49.9-1-S4  [R0402]  189.54 160.49 180 bottom
UNK2R50  49.9-1-S4  [R0402]  192.4 160.49 180 bottom
UNK2R51  49.9-1-S4  [R0402]  174.3 171.3 180 bottom
UNK2R52  49.9-1-S4  [R0402]  177.16 171.3 180 bottom
UNK2R53  49.9-1-S4  [R0402]  174.3 160.49 180 bottom
UNK2R54  49.9-1-S4  [R0402]  177.16 160.49 180 bottom
UNK2R55  49.9-1-S4  [R0402]  163.41 210.07 90 bottom
UNK2R56  49.9-1-S4  [R0402]  163.41 207.21 90 bottom
UNK2R57  49.9-1-S4  [R0402]  152.6 210.07 90 bottom
UNK2R58  49.9-1-S4  [R0402]  152.6 207.21 90 bottom
UNK2R59  49.9-1-S4  [R0402]  178.65 194.83 90 bottom
UNK2R60  49.9-1-S4  [R0402]  178.65 191.97 90 bottom
UNK2R61  49.9-1-S4  [R0402]  167.84 194.83 90 bottom
UNK2R62  49.9-1-S4  [R0402]  167.84 191.97 90 bottom
UNK2R63  49.9-1-S4  [R0402]  194.73 254.94 0 bottom
UNK2R64  49.9-1-S4  [R0402]  191.87 254.94 0 bottom
UNK2R65  49.9-1-S4  [R0402]  152.6 194.83 90 bottom
UNK2R66  49.9-1-S4  [R0402]  152.6 191.97 90 bottom
UNK2R67  49.9-1-S4  [R0402]  209.97 271.45 0 bottom
UNK2R68  49.9-1-S4  [R0402]  207.11 271.45 0 bottom
UNK2R69  49.9-1-S4  [R0402]  209.97 282.26 0 bottom
UNK2R70  49.9-1-S4  [R0402]  207.11 282.26 0 bottom
UNK2R71  49.9-1-S4  [R0402]  210.23 254.94 0 bottom
UNK2R72  49.9-1-S4  [R0402]  207.37 254.94 0 bottom
UNK2R73  49.9-1-S4  [R0402]  210.23 265.75 0 bottom
UNK2R74  49.9-1-S4  [R0402]  207.37 265.75 0 bottom
UNK2R75  49.9-1-S4  [R0402]  194.73 287.96 0 bottom
UNK2R76  49.9-1-S4  [R0402]  191.87 287.96 0 bottom
UNK2R77  49.9-1-S4  [R0402]  194.73 298.77 0 bottom
UNK2R78  49.9-1-S4  [R0402]  191.87 298.77 0 bottom
UNK2R79  49.9-1-S4  [R0402]  194.73 271.45 0 bottom
UNK2R80  49.9-1-S4  [R0402]  191.87 271.45 0 bottom
UNK2R82  4.7K-1-S4-WA  [R0402]  247.26 209.95 270 bottom
UNK2R83  4.7K-1-S4-WA  [R0402]  247.25 193.85 90 bottom
UNK2R84  4.7K-1-S4-WA  [R0402]  239.88 193.85 90 bottom
UNK2R85  100K-1-S4  [R0402]  256.47 199.78 90 bottom
UNK2R86  4.7K-1-S4-WA  [R0402]  262.07 180.49 90 bottom
UNK2R87  4.7K-1-S4-WA  [R0402]  259.85 187.23 0 bottom
UNK2R88  4.7K-1-S4-WA  [R0402]  259.85 188.37 0 bottom
UNK2R89  4.7K-1-S4-WA  [R0402]  262.07 184.57 270 bottom
UNK2R90  4.7K-1-S4-WA  [R0402]  247.67 174.02 180 bottom
UNK2R91  4.7K-1-S4-WA  [R0402]  247.67 171.48 180 bottom
UNK2R92  4.7K-1-S4-WA  [R0402]  247.67 168.94 180 bottom
UNK2R93  4.7K-1-S4-WA  [R0402]  278.74 180.49 90 bottom
UNK2R94  4.7K-1-S4-WA  [R0402]  276.51 187.23 180 bottom
UNK2R95  4.7K-1-S4-WA  [R0402]  276.51 188.37 180 bottom
UNK2R96  4.7K-1-S4-WA  [R0402]  278.74 184.57 270 bottom
UNK2R97  4.7K-1-S4-WA  [R0402]  267.38 174.02 180 bottom
UNK2R98  4.7K-1-S4-WA  [R0402]  267.38 171.48 180 bottom
UNK2R99  4.7K-1-S4-WA  [R0402]  267.38 168.94 180 bottom
UNK2R100  49.9-1-S4  [R0402]  194.73 265.75 0 bottom
UNK2R101  49.9-1-S4  [R0402]  191.87 265.75 0 bottom
UNK2R102  49.9-1-S4  [R0402]  174.3 185.53 180 bottom
UNK2R103  49.9-1-S4  [R0402]  177.16 185.53 180 bottom
UNK2R104  49.9-1-S4  [R0402]  163.41 194.83 90 bottom
UNK2R105  49.9-1-S4  [R0402]  163.41 191.97 90 bottom
UNK2R117  1K-1-S4  [R0402]  247.22 206.55 90 bottom
UNK2R118  NC/0-5-S4  [R0402]  185.9 215.39 180 top
UNK2R119  4.7K-1-S4-WA  [R0402]  243.84 177.49 270 bottom
UNK2R120  4.7K-1-S4-WA  [R0402]  236.45 177.49 270 bottom
UNK2R125  0-5-S4  [R0402]  227.36 157.81 270 bottom
UNK2R126  0-5-S4  [R0402]  227.36 153.41 270 bottom
UNK2R127  0-5-S4  [R0402]  219.99 157.81 270 bottom
UNK2R128  0-5-S4  [R0402]  219.99 153.41 270 bottom
UNK2R129  0-5-S4  [R0402]  202.76 151.56 180 bottom
UNK2R130  0-5-S4  [R0402]  200.56 151.56 0 bottom
UNK2R131  50-0.1-S4-HF-VI  [R0402]  203.76 163.88 0 bottom
UNK2R132  50-0.1-S4-HF-VI  [R0402]  199.56 163.88 180 bottom
UNK2R133  0-5-S4  [R0402]  178.38 247.99 90 bottom
UNK2RP1  0-5-S4  [R0402]  198.77 207.19 90 bottom
UNK2RP2  0-5-S4  [R0402]  197.86 211.63 0 bottom
UNK2RP3  0-5-S4  [R0402]  213.98 213.47 180 bottom
UNK2RP4  0-5-S4  [R0402]  207.57 207.19 90 bottom
UNK2RP5  0-5-S4  [R0402]  209.97 207.19 90 bottom
UNK2RP6  0-5-S4  [R0402]  213.98 219.47 180 bottom
UNK2RP7  0-5-S4  [R0402]  208.23 223.09 270 bottom
UNK2RP8  0-5-S4  [R0402]  206.12 223.09 270 bottom
